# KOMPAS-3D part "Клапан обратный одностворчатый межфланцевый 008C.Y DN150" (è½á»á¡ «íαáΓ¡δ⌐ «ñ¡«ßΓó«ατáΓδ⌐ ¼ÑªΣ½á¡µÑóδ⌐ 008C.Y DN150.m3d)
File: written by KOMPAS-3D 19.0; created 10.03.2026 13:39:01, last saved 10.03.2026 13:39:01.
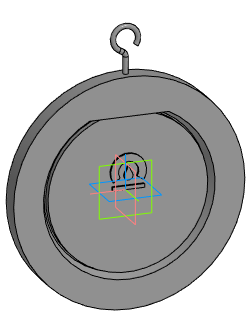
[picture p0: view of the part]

Document properties: Автор: Евгений; Полное имя файла: E:\Dendor\3D для проектировщиков\5.1 Тип 008C. Клапан обратный одностворчатый межфланцевый\stp_Клапан обратный одностворчатый межфланцевый 008C.Y\Клапан обратный одностворчатый межфланцевый 008C.Y DN150.m3d

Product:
- Part/product: Клапан обратный одностворчатый межфланцевый 008C.Y DN150

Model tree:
1. Операция без истории:1  (labels: Клапан обратный одностворчатый межфланцевый 008C.Y DN150)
